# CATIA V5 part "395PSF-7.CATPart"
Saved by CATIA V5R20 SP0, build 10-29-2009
Part number: 395PSF-7
Source: Unknown
Property "ARTICLENO": "395PSF-7"
Property "BOMINFO": "395PSF-7"
Property "CODE": "395PSF-7"
Property "D": "53.000"
Property "D1": "65.000"
Property "H": "6.000"
Property "L": "227.000"
Property "L1": "10.000"
Property "L2": "180.000"
Property "L3": "16.000"
Property "L4": "10.000"
Property "LINA": "395PSF-7"
Property "MAXLOAD": "8000 Kg"
Property "MDW": "16000 Kg"
Property "NB": "395PSF-7"
Property "NBSYN": "$CODE."
Property "NN": "395PSF"
Property "NT": "FIAT Lifting Pins"
Property "SUPPLIER": "CF"
Bounding box of the stored display mesh (mm): x 0 to 227, y -32.5 to 32.5, z -32.5 to 32.5
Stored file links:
  C:\Users\Utente\Desktop\3D files 395PSF\395PSF-7.CATPart
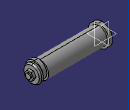
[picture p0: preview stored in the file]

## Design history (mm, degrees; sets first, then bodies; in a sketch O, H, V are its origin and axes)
Body1 "Geometry.1" (main body)
  Solid1 "395PSF-7.catpart": solid without history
